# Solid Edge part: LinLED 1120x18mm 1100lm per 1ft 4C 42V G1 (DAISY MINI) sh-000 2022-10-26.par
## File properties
Author: jaroslaw.przewlocki
Template: iso metric part.par
Last saved by: jaroslaw.przewlocki
Revision: 2
Application: Solid Edge
Gęstość: 0,000 kg/m^3
Dokładność: 0,990
Username: jaroslaw.przewlocki
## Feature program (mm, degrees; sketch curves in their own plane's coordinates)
body "unnamed Body 1"
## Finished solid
Body 1: solid body, 2342 faces, 6168 edges, 4040 vertices.
  Faces by surface: plane 2072, cylinder 194, torus 28, spline 24, cone 20, sphere 4
  Edges by curve: line 5552, circle 360, curve on surface 212, spline 44
Bounding box of the edges (mm; curved faces can reach further): 1119.300 x 4.050 x 18.000, from (-559.65, -2.45, -9) to (559.65, 1.6, 9).
Cylindrical faces by radius (mm): R0.1 x16, R0.102 x8, R0.25 x20, R0.35 x16, R0.352 x8, R0.5 x12, R0.55 x8, R0.8 x8, R0.9 x4, R1.047 x4, R1.05 x4, R1.1 x16, R1.1249 x4, R1.15 x4, R1.1515 x4, R1.2389 x4, R2 x32, R2.1734 x8, R2.5 x6, R5.6968 x4, R5.9345 x4
Conical faces (half-angle, radius in mm at the cone's reference point): 0.1529 deg R0.8961 x4, 4.0564 deg R1.1559 x4, 10.9476 deg R0.928 x4, 39.99 deg R0.9633 x4, 62.7291 deg R0.376 x4
Toroidal faces (ring radius, tube radius in mm): R-0.3126 r0.9167 x4, R0.55 r0.6 x4, R1.1764 r0.5 x4, R1.1777 r0.5 x4, R1.3 r0.5 x4, R1.4161 r0.5 x8
Spherical faces by radius (mm): R1.1446 x4
Planar faces by outward normal: +x 267, +y 17, +z 299, -x 267, -y 357, -z 301, oblique 564
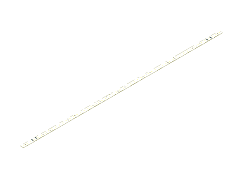
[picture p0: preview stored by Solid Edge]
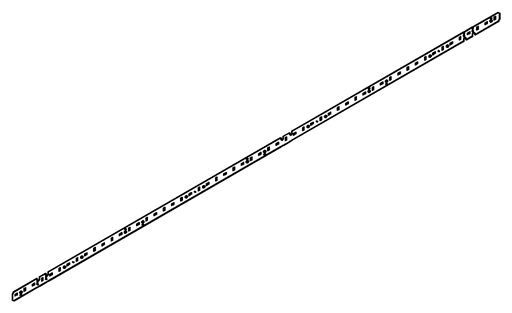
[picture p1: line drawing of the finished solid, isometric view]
